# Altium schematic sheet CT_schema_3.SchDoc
size 255 x 245 mm
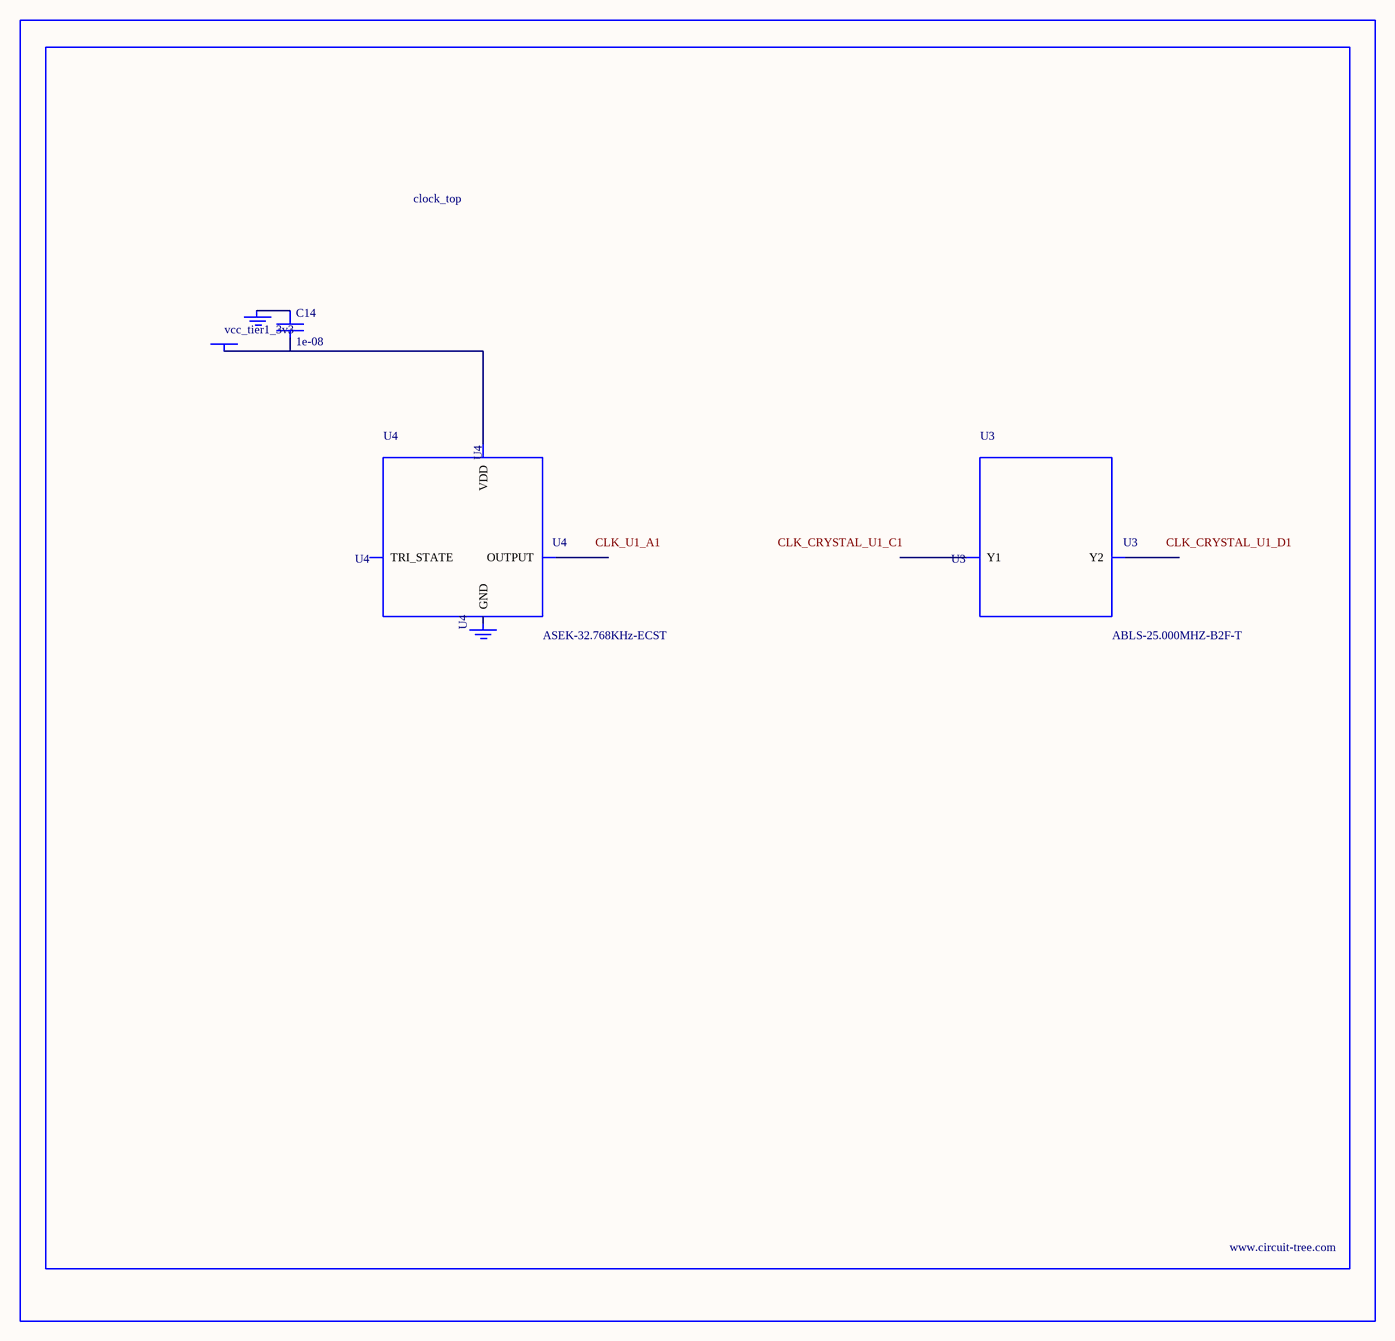
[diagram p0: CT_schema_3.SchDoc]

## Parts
BORDER2  (no value)
C14  1e-08  [C0402]
GND_INSTANCE_2_0  (no value)
GND_INSTANCE_2_1  (no value)
POWER_INSTANCE_2_0  vcc_tier1_3v3
U3  ABLS-25.000MHZ-B2F-T  [ABLS-25.000MHZ-B2F-T]
U4  ASEK-32.768KHz-ECST  [ASEK]

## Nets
NetC14_1: C14.1 GND_INSTANCE_2_0.0(GND)
NetC14_2: C14.2 POWER_INSTANCE_2_0.0(PWR) U4.4(VDD)

Not connected (* = marked no-connect by the designer): GND_INSTANCE_2_1 0(GND); U3 1(Y1) 2(Y2); U4 1(TRI_STATE) 2(GND) 3(OUTPUT)

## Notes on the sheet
- Labels drawn without touching a wire or pin: CLK_CRYSTAL_U1_C1, CLK_CRYSTAL_U1_D1, CLK_U1_A1

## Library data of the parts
BORDER2 = BORDER_PAGE2
C14 = C0402C103K3RAC
GND_INSTANCE_2_0 GND_INSTANCE_2_1 = GND
POWER_INSTANCE_2_0 = PWR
